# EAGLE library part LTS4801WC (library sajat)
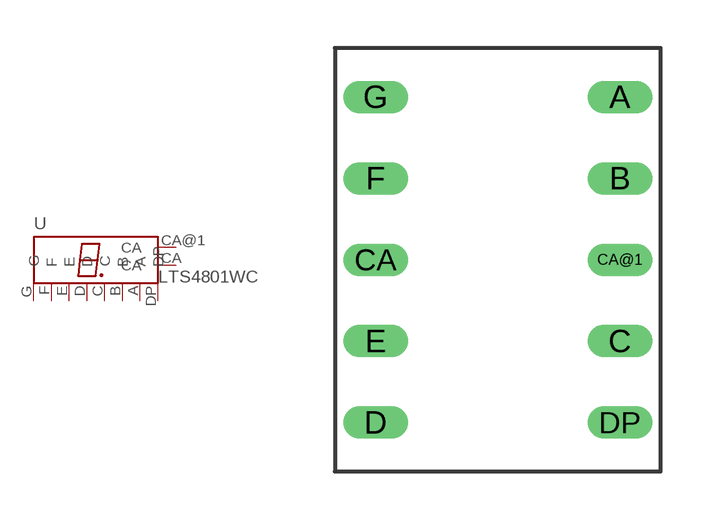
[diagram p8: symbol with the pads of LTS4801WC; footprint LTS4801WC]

Designator prefix -

## LTS4801WC  [LTS4801WC]
A  A
B  B
C  C
CA  CA
CA@1  CA
D  D
DP  DP
E  E
F  F
G  G

## Footprint LTS4801WC (pad centres in mm)
drill 0.254 pad 1.016 long: A 3.81,5.08; B 3.81,2.54; C 3.81,-2.54; CA -3.81,0; CA@1 3.81,0; D -3.81,-5.08; DP 3.81,-5.08; E -3.81,-2.54; F -3.81,2.54; G -3.81,5.08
